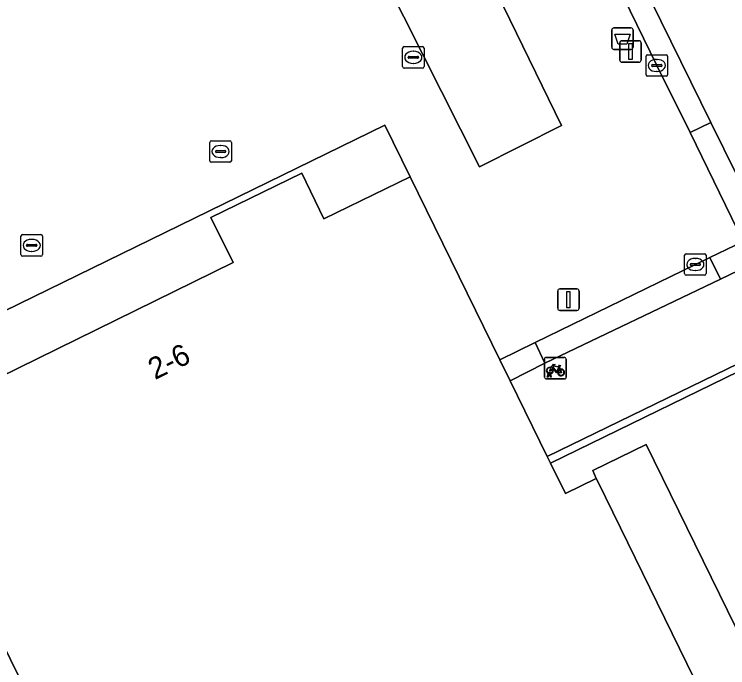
# Model space of a CAD drawing. Extents: x 160455 to 162082, y 388339 to 389736.
# Drawn here: x 160999.83 to 161032.93, y 388835.68 to 388865.99 of the extents above; entities that cross this region are included whole.
import ezdxf

# ---------------------------------------------------------------- set-up
doc = ezdxf.new("R2010")
doc.units = 0
for name, color, linetype in [('IMGEO_Afvalbak', 7, 'Continuous'), ('IMGEO_Erf', 7, 'Continuous'), ('IMGEO_Fietsenrek', 7, 'Continuous'), ('IMGEO_Groenvoorziening', 7, 'Continuous'), ('IMGEO_Kolk', 7, 'Continuous'), ('IMGEO_Lichtmast', 7, 'Continuous'), ('IMGEO_Muur', 7, 'Continuous'), ('IMGEO_Pand', 7, 'Continuous'), ('IMGEO_Pand_nummerreeks', 7, 'Continuous'), ('IMGEO_Pand_overbouw', 7, 'Continuous'), ('IMGEO_Voetgangersgebied_open', 7, 'Continuous'), ('IMGEO_Voetpad_open', 7, 'Continuous')]:
    doc.layers.add(name, color=color, linetype=linetype)

msp = doc.modelspace()

# ---------------------------------------------------------------- linework, layer by layer
at = {"layer": 'IMGEO_Afvalbak'}
for p, q in [((161027.551, 388864.457), (161027.551, 388865.257)), ((161027.551, 388865.257), (161027.551, 388864.457)), ((161027.651, 388865.357), (161028.441, 388865.357)), ((161028.441, 388865.357), (161027.651, 388865.357)), ((161028.541, 388865.257), (161028.541, 388864.457)), ((161028.541, 388864.457), (161028.541, 388865.257)), ((161028.441, 388864.357), (161027.651, 388864.357)), ((161027.651, 388864.357), (161028.441, 388864.357))]:
    msp.add_line(p, q, dxfattribs=at)
msp.add_lwpolyline([(161027.694, 388865.071), (161028.398, 388865.071), (161028.249, 388864.601), (161027.843, 388864.601), (161027.694, 388865.071)], dxfattribs=at)
for centre, start, end in [((161027.651, 388865.257), 90, 180), ((161027.651, 388865.257), 90, 180), ((161028.441, 388865.257), 0, 90), ((161028.441, 388865.257), 360, 90), ((161027.651, 388864.457), 180, 270), ((161027.651, 388864.457), 180, 270), ((161028.441, 388864.457), 270, 0), ((161028.441, 388864.457), 270, 0)]:
    msp.add_arc(centre, 0.1, start, end, dxfattribs=at)
at = {"layer": 'IMGEO_Erf'}
for points in [[(161009.991, 388854.476), (161008.95, 388856.554), (161013.176, 388858.615), (161014.196, 388856.492), (161018.202, 388858.451), (161017.024, 388860.849), (160993.231, 388849.232), (160994.388, 388846.828), (161000, 388849.579)], [(161034.808, 388828.171), (161034.896, 388827.986), (161033.464, 388827.274), (161035.073, 388823.978), (161042.285, 388827.496), (161041.106, 388829.921), (161037.828, 388828.327), (161029.15, 388846.035), (161026.674, 388844.824), (161026.833, 388844.465), (161026.923, 388844.28)]]:
    msp.add_lwpolyline(points, close=True, dxfattribs=at)
at = {"layer": 'IMGEO_Fietsenrek'}
for p, q in [((161024.433, 388849.149), (161024.433, 388849.99)), ((161024.433, 388849.99), (161024.433, 388849.149)), ((161024.508, 388850.074), (161025.349, 388850.074)), ((161025.349, 388850.074), (161024.508, 388850.074)), ((161025.433, 388849.999), (161025.433, 388849.158)), ((161025.433, 388849.158), (161025.433, 388849.999)), ((161025.12, 388849.623), (161025.156, 388849.528)), ((161024.56, 388849.158), (161024.599, 388849.318)), ((161024.629, 388849.306), (161024.594, 388849.158)), ((161024.671, 388849.33), (161024.67, 388849.334)), ((161024.712, 388849.158), (161024.678, 388849.3)), ((161024.702, 388849.341), (161024.703, 388849.334)), ((161024.71, 388849.304), (161024.745, 388849.158)), ((161025.358, 388849.074), (161024.517, 388849.074)), ((161024.517, 388849.074), (161025.358, 388849.074)), ((161024.594, 388849.158), (161024.56, 388849.158)), ((161024.745, 388849.158), (161024.712, 388849.158))]:
    msp.add_line(p, q, dxfattribs=at)
for points in [[(161024.767, 388849.548), (161024.715, 388849.458), (161024.675, 388849.433), (161024.676, 388849.48), (161024.731, 388849.574)], [(161024.746, 388849.6), (161024.841, 388849.764), (161024.927, 388849.75), (161024.929, 388849.741), (161024.873, 388849.73), (161024.846, 388849.685), (161025.102, 388849.644)], [(161025.042, 388849.356), (161024.992, 388849.356), (161024.801, 388849.607), (161024.782, 388849.575)], [(161025.089, 388849.619), (161024.832, 388849.66), (161024.815, 388849.631), (161024.982, 388849.411), (161025.089, 388849.619)], [(161025.137, 388849.521), (161025.107, 388849.598), (161024.998, 388849.38), (161025.041, 388849.38)], [(161025.102, 388849.644), (161025.127, 388849.693), (161025.121, 388849.697), (161025.098, 388849.701), (161025.086, 388849.708), (161025.085, 388849.711), (161025.087, 388849.716), (161025.182, 388849.701), (161025.184, 388849.691), (161025.174, 388849.678), (161025.162, 388849.672), (161025.148, 388849.678), (161025.12, 388849.623)], [(161025.071, 388849.38), (161025.191, 388849.379), (161025.147, 388849.493)], [(161025.167, 388849.5), (161025.222, 388849.355), (161025.072, 388849.355)]]:
    msp.add_lwpolyline(points, dxfattribs=at)
for centre, radius, start, end in [((161024.511, 388849.996), 0.0779, 92.4484, 184.2845), ((161024.511, 388849.996), 0.0779, 92.4484, 184.2845), ((161025.355, 388849.996), 0.0779, 2.4484, 94.2845), ((161025.355, 388849.996), 0.0779, 2.4484, 94.2845), ((161024.673, 388849.459), 0.159, 62.6766, 242.1369), ((161024.673, 388849.459), 0.129, 63.3192, 238.903), ((161024.673, 388849.459), 0.159, 283.5766, 46.6042), ((161024.653, 388849.33), 0.0499, 12.8025, 158.6934), ((161024.673, 388849.459), 0.159, 253.9967, 271.7867), ((161024.653, 388849.33), 0.0174, 12.8025, 163.4502), ((161024.673, 388849.459), 0.129, 253.415, 269.0204), ((161024.673, 388849.459), 0.129, 283.6043, 43.4302), ((161025.2, 388849.375), 0.159, 113.3408, 178.3217), ((161025.2, 388849.375), 0.159, 187.0065, 105.7708), ((161025.2, 388849.375), 0.129, 113.923, 177.9556), ((161025.2, 388849.375), 0.129, 188.6715, 104.5883), ((161024.511, 388849.152), 0.0779, 182.4484, 274.2845), ((161024.511, 388849.152), 0.0779, 182.4484, 274.2845), ((161025.355, 388849.152), 0.0779, 272.4484, 4.2845), ((161025.355, 388849.152), 0.0779, 272.4484, 4.2845)]:
    msp.add_arc(centre, radius, start, end, dxfattribs=at)
at = {"layer": 'IMGEO_Groenvoorziening'}
msp.add_lwpolyline([(161015.259, 388871.119), (161021.414, 388858.916), (161025.216, 388860.835), (161019.226, 388873.12)], close=True, dxfattribs=at)
at = {"layer": 'IMGEO_Kolk'}
for p, q in [((161017.918, 388864.488), (161018.77, 388864.488)), ((161017.843, 388863.562), (161017.843, 388864.414)), ((161018.331, 388864.268), (161018.356, 388864.268)), ((161018.844, 388864.414), (161018.844, 388863.562)), ((161018.102, 388863.982), (161018.102, 388863.994)), ((161018.54, 388863.945), (161018.142, 388863.945)), ((161018.145, 388864.031), (161018.543, 388864.031)), ((161018.586, 388863.994), (161018.586, 388863.982)), ((161029.141, 388863.185), (161029.141, 388864.037)), ((161029.216, 388864.111), (161030.068, 388864.111)), ((161029.629, 388863.891), (161029.654, 388863.891)), ((161030.142, 388864.037), (161030.142, 388863.185)), ((161018.77, 388863.488), (161017.918, 388863.488)), ((161018.354, 388863.708), (161018.329, 388863.708)), ((161029.4, 388863.605), (161029.4, 388863.617)), ((161029.838, 388863.568), (161029.44, 388863.568)), ((161029.443, 388863.654), (161029.841, 388863.654)), ((161029.884, 388863.617), (161029.884, 388863.605)), ((161029.652, 388863.331), (161029.627, 388863.331)), ((161030.068, 388863.111), (161029.216, 388863.111)), ((161008.901, 388859.195), (161008.901, 388860.047)), ((161008.976, 388860.121), (161009.828, 388860.121)), ((161009.389, 388859.901), (161009.414, 388859.901)), ((161009.902, 388860.047), (161009.902, 388859.195)), ((161009.16, 388859.615), (161009.16, 388859.627)), ((161009.598, 388859.578), (161009.2, 388859.578)), ((161009.203, 388859.664), (161009.601, 388859.664)), ((161009.644, 388859.627), (161009.644, 388859.615)), ((161009.412, 388859.341), (161009.387, 388859.341)), ((161009.828, 388859.121), (161008.976, 388859.121)), ((161000.135, 388854.843), (161000.135, 388855.695)), ((161000.21, 388855.769), (161001.062, 388855.769)), ((161000.623, 388855.549), (161000.648, 388855.549)), ((161001.136, 388855.695), (161001.136, 388854.843)), ((161000.394, 388855.263), (161000.394, 388855.275)), ((161000.832, 388855.226), (161000.434, 388855.226)), ((161000.437, 388855.312), (161000.835, 388855.312)), ((161000.878, 388855.275), (161000.878, 388855.263)), ((161000.646, 388854.989), (161000.621, 388854.989)), ((161031.004, 388854.883), (161031.856, 388854.883)), ((161001.062, 388854.769), (161000.21, 388854.769)), ((161030.929, 388853.957), (161030.929, 388854.809)), ((161031.417, 388854.663), (161031.442, 388854.663)), ((161031.93, 388854.809), (161031.93, 388853.957)), ((161031.188, 388854.377), (161031.188, 388854.389)), ((161031.626, 388854.34), (161031.228, 388854.34)), ((161031.231, 388854.426), (161031.629, 388854.426)), ((161031.672, 388854.389), (161031.672, 388854.377)), ((161031.856, 388853.883), (161031.004, 388853.883)), ((161031.44, 388854.103), (161031.415, 388854.103))]:
    msp.add_line(p, q, dxfattribs=at)
for points in [[(161017.918, 388864.488), (161018.77, 388864.488)], [(161017.843, 388863.562), (161017.843, 388864.414)], [(161018.844, 388864.414), (161018.844, 388863.562)], [(161029.141, 388863.185), (161029.141, 388864.037)], [(161029.216, 388864.111), (161030.068, 388864.111)], [(161030.142, 388864.037), (161030.142, 388863.185)], [(161018.77, 388863.488), (161017.918, 388863.488)], [(161030.068, 388863.111), (161029.216, 388863.111)], [(161008.901, 388859.195), (161008.901, 388860.047)], [(161008.976, 388860.121), (161009.828, 388860.121)], [(161009.902, 388860.047), (161009.902, 388859.195)], [(161009.828, 388859.121), (161008.976, 388859.121)], [(161000.135, 388854.843), (161000.135, 388855.695)], [(161000.21, 388855.769), (161001.062, 388855.769)], [(161001.136, 388855.695), (161001.136, 388854.843)], [(161031.004, 388854.883), (161031.856, 388854.883)], [(161001.062, 388854.769), (161000.21, 388854.769)], [(161030.929, 388853.957), (161030.929, 388854.809)], [(161031.93, 388854.809), (161031.93, 388853.957)], [(161031.856, 388853.883), (161031.004, 388853.883)]]:
    msp.add_lwpolyline(points, dxfattribs=at)
for centre, radius, start, end in [((161017.92, 388864.412), 0.0765, 91.552, 178.448), ((161017.92, 388864.412), 0.0765, 91.552, 178.448), ((161018.768, 388864.412), 0.0765, 1.552, 88.448), ((161018.768, 388864.412), 0.0765, 1.552, 88.448), ((161018.142, 388863.991), 0.0403, 85.8775, 175.7526), ((161018.139, 388863.981), 0.0366, 178.938, 274.7102), ((161018.543, 388863.988), 0.043, 264.8664, 352.4533), ((161018.547, 388863.993), 0.0386, 1.7309, 96.639), ((161029.218, 388864.035), 0.0765, 91.552, 178.448), ((161029.218, 388864.035), 0.0765, 91.552, 178.448), ((161030.066, 388864.035), 0.0765, 1.552, 88.448), ((161030.066, 388864.035), 0.0765, 1.552, 88.448), ((161017.92, 388863.564), 0.0765, 181.552, 268.448), ((161017.92, 388863.564), 0.0765, 181.552, 268.448), ((161018.768, 388863.564), 0.0765, 271.552, 358.448), ((161018.768, 388863.564), 0.0765, 271.552, 358.448), ((161029.44, 388863.614), 0.0403, 85.8775, 175.7526), ((161029.437, 388863.604), 0.0366, 178.938, 274.7102), ((161029.841, 388863.611), 0.043, 264.8664, 352.4533), ((161029.845, 388863.616), 0.0386, 1.7309, 96.639), ((161029.218, 388863.187), 0.0765, 181.552, 268.448), ((161029.218, 388863.187), 0.0765, 181.552, 268.448), ((161030.066, 388863.187), 0.0765, 271.552, 358.448), ((161030.066, 388863.187), 0.0765, 271.552, 358.448), ((161008.978, 388860.045), 0.0765, 91.552, 178.448), ((161008.978, 388860.045), 0.0765, 91.552, 178.448), ((161009.826, 388860.045), 0.0765, 1.552, 88.448), ((161009.826, 388860.045), 0.0765, 1.552, 88.448), ((161009.2, 388859.624), 0.0403, 85.8775, 175.7526), ((161009.197, 388859.614), 0.0366, 178.938, 274.7102), ((161009.601, 388859.621), 0.043, 264.8664, 352.4533), ((161009.605, 388859.626), 0.0386, 1.7309, 96.639), ((161008.978, 388859.197), 0.0765, 181.552, 268.448), ((161008.978, 388859.197), 0.0765, 181.552, 268.448), ((161009.826, 388859.197), 0.0765, 271.552, 358.448), ((161009.826, 388859.197), 0.0765, 271.552, 358.448), ((161000.212, 388855.693), 0.0765, 91.552, 178.448), ((161000.212, 388855.693), 0.0765, 91.552, 178.448), ((161001.06, 388855.693), 0.0765, 1.552, 88.448), ((161001.06, 388855.693), 0.0765, 1.552, 88.448), ((161000.434, 388855.272), 0.0403, 85.8775, 175.7526), ((161000.431, 388855.262), 0.0366, 178.938, 274.7102), ((161000.835, 388855.269), 0.043, 264.8664, 352.4533), ((161000.839, 388855.274), 0.0386, 1.7309, 96.639), ((161031.006, 388854.807), 0.0765, 91.552, 178.448), ((161031.006, 388854.807), 0.0765, 91.552, 178.448), ((161031.854, 388854.807), 0.0765, 1.552, 88.448), ((161031.854, 388854.807), 0.0765, 1.552, 88.448), ((161000.212, 388854.845), 0.0765, 181.552, 268.448), ((161000.212, 388854.845), 0.0765, 181.552, 268.448), ((161001.06, 388854.845), 0.0765, 271.552, 358.448), ((161001.06, 388854.845), 0.0765, 271.552, 358.448), ((161031.228, 388854.386), 0.0403, 85.8775, 175.7526), ((161031.225, 388854.376), 0.0366, 178.938, 274.7102), ((161031.629, 388854.383), 0.043, 264.8664, 352.4533), ((161031.633, 388854.388), 0.0386, 1.7309, 96.639), ((161031.006, 388853.959), 0.0765, 181.552, 268.448), ((161031.006, 388853.959), 0.0765, 181.552, 268.448), ((161031.854, 388853.959), 0.0765, 271.552, 358.448), ((161031.854, 388853.959), 0.0765, 271.552, 358.448)]:
    msp.add_arc(centre, radius, start, end, dxfattribs=at)
for centre, major_axis, ratio, start_param, end_param in [((161018.33, 388863.988), (-0.387, 0.002), 0.722429, 4.712389, 7.853982), ((161018.355, 388863.988), (-0.39, 0.002), 0.717154, 1.570796, 4.712389), ((161029.628, 388863.611), (-0.387, 0.002), 0.722429, 4.712389, 7.853982), ((161029.653, 388863.611), (-0.39, 0.002), 0.717154, 1.570796, 4.712389), ((161009.388, 388859.621), (-0.387, 0.002), 0.722429, 4.712389, 7.853982), ((161009.413, 388859.621), (-0.39, 0.002), 0.717154, 1.570796, 4.712389), ((161000.622, 388855.269), (-0.387, 0.002), 0.722429, 4.712389, 7.853982), ((161000.647, 388855.269), (-0.39, 0.002), 0.717154, 1.570796, 4.712389), ((161031.416, 388854.383), (-0.387, 0.002), 0.722429, 4.712389, 7.853982), ((161031.441, 388854.383), (-0.39, 0.002), 0.717154, 1.570796, 4.712389)]:
    msp.add_ellipse(centre, major_axis=major_axis, ratio=ratio, start_param=start_param, end_param=end_param, dxfattribs=at)
at = {"layer": 'IMGEO_Lichtmast'}
for p, q in [((161027.922, 388863.861), (161027.922, 388864.661)), ((161027.922, 388864.661), (161027.922, 388863.861)), ((161028.022, 388864.761), (161028.812, 388864.761)), ((161028.812, 388864.761), (161028.022, 388864.761)), ((161028.912, 388864.661), (161028.912, 388863.861)), ((161028.912, 388863.861), (161028.912, 388864.661)), ((161028.812, 388863.761), (161028.022, 388863.761)), ((161028.022, 388863.761), (161028.812, 388863.761)), ((161025.142, 388853.251), (161025.932, 388853.251)), ((161025.932, 388853.251), (161025.142, 388853.251)), ((161025.042, 388852.351), (161025.042, 388853.151)), ((161025.042, 388853.151), (161025.042, 388852.351)), ((161026.032, 388853.151), (161026.032, 388852.351)), ((161026.032, 388852.351), (161026.032, 388853.151)), ((161025.932, 388852.251), (161025.142, 388852.251)), ((161025.142, 388852.251), (161025.932, 388852.251))]:
    msp.add_line(p, q, dxfattribs=at)
for points in [[(161028.342, 388864.636), (161028.492, 388864.636), (161028.492, 388863.886), (161028.342, 388863.886), (161028.342, 388864.636)], [(161025.462, 388853.126), (161025.612, 388853.126), (161025.612, 388852.376), (161025.462, 388852.376), (161025.462, 388853.126)]]:
    msp.add_lwpolyline(points, dxfattribs=at)
for centre, start, end in [((161028.022, 388864.661), 90, 180), ((161028.022, 388864.661), 90, 180), ((161028.812, 388864.661), 0, 90), ((161028.812, 388864.661), 360, 90), ((161028.022, 388863.861), 180, 270), ((161028.022, 388863.861), 180, 270), ((161028.812, 388863.861), 270, 0), ((161028.812, 388863.861), 270, 0), ((161025.142, 388853.151), 90, 180), ((161025.142, 388853.151), 90, 180), ((161025.932, 388853.151), 0, 90), ((161025.932, 388853.151), 360, 90), ((161025.142, 388852.351), 180, 270), ((161025.142, 388852.351), 180, 270), ((161025.932, 388852.351), 270, 0), ((161025.932, 388852.351), 270, 0)]:
    msp.add_arc(centre, 0.1, start, end, dxfattribs=at)
at = {"layer": 'IMGEO_Muur'}
msp.add_lwpolyline([(161041.11, 388853.151), (161039.679, 388856.145), (161039.373, 388855.998), (161040.679, 388853.319), (161024.557, 388845.477), (161024.71, 388845.165), (161035.31, 388850.339), (161037.267, 388851.277), (161041.013, 388853.104)], close=True, dxfattribs=at)
at = {"layer": 'IMGEO_Pand'}
msp.add_lwpolyline([(161034.808, 388828.171), (161026.923, 388844.28), (161026.833, 388844.465), (161025.4, 388843.757), (161024.71, 388845.165), (161024.557, 388845.477), (161022.835, 388848.993), (161022.36, 388849.963), (161018.202, 388858.451), (161014.196, 388856.492), (161013.176, 388858.615), (161008.95, 388856.554), (161009.991, 388854.476), (161000, 388849.579), (160994.388, 388846.828), (160998.437, 388838.503), (160998.917, 388837.546), (161000, 388835.333)], dxfattribs=at)
at = {"layer": 'IMGEO_Pand_overbouw'}
msp.add_lwpolyline([(160994.388, 388846.828), (161000, 388849.579), (161009.991, 388854.476), (161008.95, 388856.554), (161013.176, 388858.615), (161014.196, 388856.492), (161018.202, 388858.451), (161017.024, 388860.849), (160993.231, 388849.232)], close=True, dxfattribs=at)
at = {"layer": 'IMGEO_Voetgangersgebied_open'}
for points in [[(161014.199, 388897.674), (161017.132, 388891.713), (161018.833, 388888.244), (161020.285, 388885.239), (161023.441, 388878.762), (161025.809, 388873.902), (161025.956, 388873.62), (161028.439, 388868.528), (161032.15, 388860.965), (161035.133, 388854.927), (161032.594, 388853.709), (161024.453, 388849.805), (161022.835, 388848.993), (161024.557, 388845.477), (161040.679, 388853.319)], [(160993.231, 388849.232), (161017.024, 388860.849), (161018.202, 388858.451), (161022.36, 388849.963), (161023.99, 388850.767), (161031.431, 388854.382), (161032.104, 388854.699), (161033.656, 388855.442), (161031.19, 388860.496), (161029.643, 388863.612), (161027.472, 388868.057), (161024.85, 388873.434), (161022.468, 388878.28), (161022.108, 388879.053), (161019.311, 388884.774), (161016.155, 388891.246), (161015.666, 388892.264), (161013.227, 388897.198)]]:
    msp.add_lwpolyline(points, dxfattribs=at)
msp.add_lwpolyline([(161015.259, 388871.119), (161019.226, 388873.12), (161025.216, 388860.835), (161021.414, 388858.916)], close=True, dxfattribs=at)
at = {"layer": 'IMGEO_Voetpad_open'}
for points in [[(161028.439, 388868.528), (161027.472, 388868.057), (161029.643, 388863.612), (161031.19, 388860.496), (161032.15, 388860.965)], [(161032.104, 388854.699), (161032.594, 388853.709), (161035.133, 388854.927), (161032.15, 388860.965), (161031.19, 388860.496), (161033.656, 388855.442)], [(161024.453, 388849.805), (161032.594, 388853.709), (161032.104, 388854.699), (161031.431, 388854.382), (161023.99, 388850.767)], [(161022.36, 388849.963), (161022.835, 388848.993), (161024.453, 388849.805), (161023.99, 388850.767)]]:
    msp.add_lwpolyline(points, close=True, dxfattribs=at)
for points in [[(161035.31, 388850.339), (161024.71, 388845.165), (161025.4, 388843.757), (161026.833, 388844.465), (161026.674, 388844.824), (161029.15, 388846.035), (161037.828, 388828.327)], [(161010.338, 388814.21), (161008.468, 388813.304), (161004.588, 388821.247), (161006.449, 388822.157), (161000, 388835.333), (160998.917, 388837.546), (160994.813, 388835.553), (161000, 388824.949), (161016.943, 388790.314), (161018.227, 388787.693), (161021.087, 388781.853), (161021.707, 388780.587)]]:
    msp.add_lwpolyline(points, dxfattribs=at)

# ---------------------------------------------------------------- texts
at = {"layer": 'IMGEO_Pand_nummerreeks'}
msp.add_text('2-6', height=1, rotation=26.0152, dxfattribs=at).set_placement((161006.352, 388849.018))

doc.saveas('drawing.dxf')
